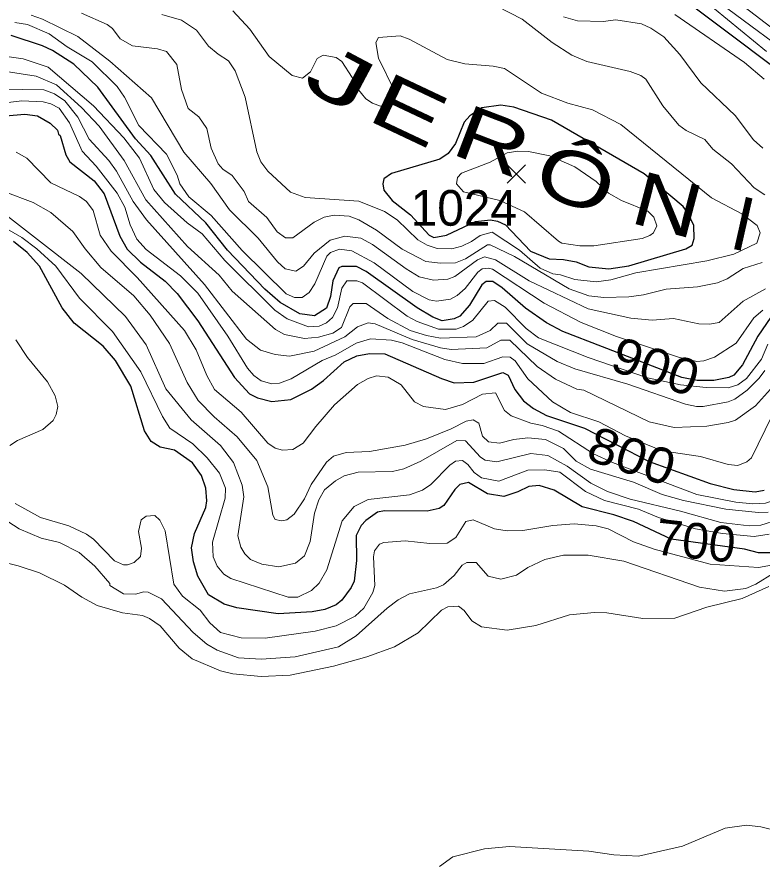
# Model space of a CAD drawing. Extents: x 265 to 291.4, y 7731.5 to 7759.6.
# Drawn here: x 280.28 to 281.951, y 7755.701 to 7757.596 of the extents above; entities that cross this region are included whole.
import ezdxf
from ezdxf.enums import TextEntityAlignment as Align

# ---------------------------------------------------------------- set-up
doc = ezdxf.new("R2010")
doc.units = 0
doc.header["$LTSCALE"] = 0.032
for name, color, linetype, lineweight in [('1', 7, 'Continuous', 25), ('2', 7, 'Continuous', 13), ('21', 7, 'Continuous', 25), ('61', 7, 'Continuous', 13)]:
    doc.layers.add(name, color=color, linetype=linetype, lineweight=lineweight)

msp = doc.modelspace()

# ---------------------------------------------------------------- linework, layer by layer
at = {"layer": '1'}
for points in [[(280.6399, 7758.3559), (280.6709, 7758.3105), (280.69, 7758.297), (280.7163, 7758.2843), (280.8165, 7758.2652), (280.8658, 7758.2413), (280.9358, 7758.1944), (281.0393, 7758.1172), (281.0885, 7758.0679), (281.149, 7758.0265), (281.2429, 7757.9534), (281.3081, 7757.8794), (281.3622, 7757.8332), (281.4099, 7757.8133), (281.5325, 7757.7958), (281.585, 7757.772), (281.6398, 7757.729), (281.7313, 7757.6693), (281.9867, 7757.4761)], [(281.9707, 7756.9224), (281.9413, 7756.8795), (281.9071, 7756.8158), (281.8872, 7756.7927), (281.8761, 7756.7872), (281.8427, 7756.7808), (281.8053, 7756.7808), (281.7712, 7756.7874), (281.5038, 7756.8906), (281.4672, 7756.9097), (281.4203, 7756.9423), (281.3678, 7756.9884), (281.3471, 7757.0027), (281.332, 7757.0027), (281.3224, 7756.9948), (281.2946, 7756.9495), (281.2731, 7756.9248), (281.2604, 7756.9184), (281.2333, 7756.9144), (281.2127, 7756.9224), (281.1776, 7756.9431), (281.0631, 7757.025), (281.0416, 7757.0361), (281.009, 7757.0361), (281.0019, 7757.033), (280.9883, 7757.0036), (280.9835, 7756.9686), (280.974, 7756.9423), (280.9477, 7756.9256), (280.9144, 7756.9303), (280.8706, 7756.955), (280.8364, 7756.9853), (280.7521, 7757.0728), (280.7035, 7757.134), (280.6359, 7757.1984), (280.5802, 7757.2852), (280.546, 7757.3225), (280.4617, 7757.4379), (280.4076, 7757.4896), (280.3599, 7757.5206), (280.3376, 7757.5309), (280.2676, 7757.554)], [(280.2549, 7757.3742), (280.2979, 7757.3774), (280.3265, 7757.3742), (280.3551, 7757.3575), (280.371, 7757.3416), (280.3734, 7757.3329), (280.3774, 7757.3297), (280.3901, 7757.2868), (280.3988, 7757.2708), (280.4538, 7757.2279), (280.476, 7757.1992), (280.511, 7757.1038), (280.5277, 7757.0752), (280.5572, 7757.0457), (280.6129, 7757.0035), (280.6399, 7756.9757), (280.686, 7756.9145), (280.768, 7756.7872), (280.8014, 7756.7506), (280.8197, 7756.7418), (280.8515, 7756.7331), (280.8945, 7756.7378), (280.9406, 7756.7609), (280.9676, 7756.7808), (281.0138, 7756.8222), (281.0424, 7756.8357), (281.0711, 7756.8413), (281.1053, 7756.8405), (281.2318, 7756.7848), (281.2604, 7756.7752), (281.3049, 7756.7768), (281.3693, 7756.7983), (281.3813, 7756.7927), (281.3964, 7756.7601), (281.4163, 7756.7346), (281.4386, 7756.7179), (281.4672, 7756.702), (281.5531, 7756.6734), (281.6977, 7756.5989), (281.8347, 7756.5493), (281.8872, 7756.5358), (281.935, 7756.531), (281.9557, 7756.5342)], [(281.3718, 7756.5207), (281.3352, 7756.5262), (281.293, 7756.5517), (281.2731, 7756.5469), (281.262, 7756.5358), (281.2373, 7756.5), (281.227, 7756.4936), (281.1999, 7756.4873), (281.1045, 7756.4881), (281.0886, 7756.4849), (281.0623, 7756.4666), (281.052, 7756.4554), (281.0408, 7756.4332), (281.0416, 7756.3767), (281.036, 7756.3306), (281.0297, 7756.3163), (281.009, 7756.2876), (280.9963, 7756.2773), (280.9708, 7756.2669), (280.9422, 7756.2614), (280.8658, 7756.2574), (280.7736, 7756.2709), (280.7449, 7756.2789), (280.7099, 7756.2996), (280.686, 7756.3417), (280.6765, 7756.3735), (280.6717, 7756.4054), (280.6781, 7756.4372), (280.7035, 7756.496), (280.7059, 7756.5104), (280.7035, 7756.539), (280.694, 7756.5676), (280.6741, 7756.5955), (280.6335, 7756.6241), (280.6017, 7756.6312), (280.581, 7756.644), (280.5667, 7756.6679), (280.5357, 7756.7681), (280.5015, 7756.8254), (280.4736, 7756.8572), (280.4084, 7756.9089), (280.3814, 7756.9431), (280.3312, 7757.037), (280.3034, 7757.0672), (280.2724, 7757.0918)], [(281.6184, 7756.4793), (281.5476, 7756.4968), (281.4847, 7756.5342), (281.4513, 7756.5453), (281.4282, 7756.543), (281.4036, 7756.531), (281.3718, 7756.5207)], [(281.9859, 7756.3942), (281.9429, 7756.3942), (281.9113, 7756.4021), (281.747, 7756.4247), (281.6629, 7756.4642), (281.6184, 7756.4793)]]:
    msp.add_lwpolyline(points, dxfattribs=at)
msp.add_lwpolyline([(281.2431, 7757.106), (281.3082, 7757.1372), (281.342, 7757.1406), (281.358, 7757.1379), (281.3759, 7757.1293), (281.4318, 7757.0708), (281.4736, 7757.0529), (281.5054, 7757.0521), (281.534, 7757.0465), (281.5627, 7757.0354), (281.6072, 7757.0306), (281.6518, 7757.0377), (281.7798, 7757.0759), (281.7942, 7757.0839), (281.7989, 7757.099), (281.7981, 7757.1277), (281.7846, 7757.1563), (281.7742, 7757.1706), (281.6868, 7757.2438), (281.4791, 7757.3639), (281.394, 7757.3933), (281.3654, 7757.3981), (281.3224, 7757.3917), (281.2954, 7757.3742), (281.2826, 7757.3599), (281.2636, 7757.3122), (281.2468, 7757.2891), (281.2286, 7757.2764), (281.1204, 7757.2446), (281.1029, 7757.2326), (281.1005, 7757.2215), (281.1029, 7757.2072), (281.1219, 7757.1841), (281.1625, 7757.1523), (281.2047, 7757.1061), (281.215, 7757.1014)], close=True, dxfattribs=at)
at = {"layer": '2'}
for points in [[(281.5993, 7757.8173), (281.7902, 7757.6805), (281.8252, 7757.6503), (281.9914, 7757.527)], [(282.0058, 7757.5461), (281.7822, 7757.7179)], [(281.9604, 7757.5182), (281.7568, 7757.6861)], [(281.9509, 7757.0449), (281.9087, 7757.0314), (281.8729, 7757.0083), (281.8506, 7756.9996), (281.8061, 7756.9908), (281.7361, 7756.9853), (281.6852, 7756.9725), (281.6518, 7756.9677), (281.5961, 7756.9669), (281.5627, 7756.9701), (281.5181, 7756.986), (281.3956, 7757.0584), (281.3415, 7757.0847), (281.3352, 7757.0847), (281.2859, 7757.0529), (281.2636, 7757.0441), (281.2302, 7757.0433), (281.1968, 7757.0473), (281.1443, 7757.0751), (281.0862, 7757.1173), (281.0472, 7757.1404), (281.0249, 7757.1491), (280.9915, 7757.1515), (280.9693, 7757.1467), (280.947, 7757.1356), (280.8992, 7757.1006), (280.8825, 7757.1006), (280.8634, 7757.1141), (280.8404, 7757.1459), (280.7998, 7757.1817), (280.7895, 7757.204), (280.7632, 7757.2398), (280.7417, 7757.2541), (280.7314, 7757.2661), (280.7155, 7757.3011), (280.7059, 7757.3456), (280.6884, 7757.3719), (280.6646, 7757.3902), (280.6494, 7757.4331), (280.6391, 7757.4888), (280.6153, 7757.5182), (280.5954, 7757.5238), (280.5397, 7757.531), (280.5118, 7757.5468), (280.4943, 7757.5699), (280.4824, 7757.5787), (280.4251, 7757.6041)], [(280.6049, 7757.601), (280.6495, 7757.5882), (280.6829, 7757.5659), (280.7099, 7757.5302), (280.7314, 7757.5119), (280.7545, 7757.4975), (280.7696, 7757.4745), (280.7918, 7757.4156), (280.8181, 7757.2931), (280.8268, 7757.2708), (280.8428, 7757.2502), (280.8936, 7757.2024), (280.9263, 7757.1905), (281.0472, 7757.1825), (281.1045, 7757.1595), (281.1331, 7757.1404), (281.1792, 7757.0958), (281.1999, 7757.0839), (281.2222, 7757.0767), (281.2556, 7757.0759), (281.2779, 7757.0815), (281.2994, 7757.0918), (281.3185, 7757.1054), (281.3455, 7757.1133), (281.4068, 7757.0727), (281.453, 7757.0322), (281.4815, 7757.0196), (281.499, 7757.0171), (281.5309, 7757.0067), (281.5786, 7757.002), (281.612, 7757.0059), (281.6677, 7757.0218), (281.8268, 7757.0489), (281.8872, 7757.064), (281.9389, 7757.0887), (281.9469, 7757.1117), (281.9397, 7757.1277), (281.9055, 7757.1539), (281.8371, 7757.1897), (281.6343, 7757.3544), (281.5706, 7757.387), (281.515, 7757.4021), (281.4561, 7757.4251), (281.3734, 7757.48), (281.3479, 7757.4856), (281.2843, 7757.4904), (281.2445, 7757.4999), (281.1594, 7757.5461), (281.1395, 7757.5532), (281.091, 7757.5493), (281.0846, 7757.5381), (281.0909, 7757.5031), (281.1275, 7757.4283), (281.1259, 7757.4116), (281.1164, 7757.4005), (281.0957, 7757.3957), (281.0774, 7757.4021), (281.0623, 7757.4124), (281.0432, 7757.4363), (281.0321, 7757.4602), (281.009, 7757.496), (280.9963, 7757.5047), (280.9669, 7757.5103), (280.9533, 7757.5023), (280.9382, 7757.4729), (280.9207, 7757.4586), (280.8977, 7757.4641), (280.8459, 7757.5071), (280.8022, 7757.5684), (280.764, 7757.6097)], [(281.3574, 7757.6192), (281.4131, 7757.5906), (281.48, 7757.5381), (281.5245, 7757.5103), (281.5579, 7757.496), (281.655, 7757.4737), (281.6788, 7757.4641), (281.69, 7757.4562), (281.7281, 7757.3965), (281.7639, 7757.3528), (281.7806, 7757.3408), (281.8228, 7757.3209), (281.8403, 7757.2995), (281.8825, 7757.2661), (281.9334, 7757.2128), (281.9572, 7757.1968)], [(280.3122, 7757.5994), (280.3376, 7757.5906), (280.4172, 7757.5516), (280.4888, 7757.4967), (280.5818, 7757.414), (280.6542, 7757.2923), (280.7147, 7757.2223), (280.7568, 7757.1634), (280.8213, 7757.0998), (280.8642, 7757.0465), (280.8817, 7757.0306), (280.9056, 7757.0258), (280.9231, 7757.037), (280.947, 7757.0656)], [(281.9525, 7757.3011), (281.9318, 7757.3202), (281.8904, 7757.3743), (281.8132, 7757.4482), (281.7663, 7757.5111), (281.7305, 7757.5508), (281.7011, 7757.5707), (281.6804, 7757.5803), (281.6231, 7757.589), (281.5945, 7757.5858), (281.5372, 7757.5866), (281.5054, 7757.5962)], [(281.7552, 7757.601), (281.9111, 7757.4936), (281.9556, 7757.4562)], [(280.9485, 7756.9972), (280.9358, 7756.9781), (280.9199, 7756.9669), (280.9024, 7756.9669), (280.8841, 7756.9749), (280.7855, 7757.072), (280.7155, 7757.1507), (280.6654, 7757.1921), (280.6455, 7757.2215), (280.6399, 7757.2406), (280.616, 7757.2883), (280.554, 7757.352), (280.5214, 7757.4156), (280.5047, 7757.4395), (280.449, 7757.4952), (280.3933, 7757.5286), (280.3527, 7757.558), (280.3042, 7757.5787), (280.2756, 7757.5835)], [(280.2629, 7757.5063), (280.2947, 7757.5015), (280.3504, 7757.4832), (280.4522, 7757.3965), (280.5198, 7757.3249), (280.5548, 7757.2788), (280.5874, 7757.2088), (280.6113, 7757.1793), (280.6622, 7757.134), (280.6956, 7757.1093)], [(281.9572, 7756.8031), (281.9445, 7756.7856), (281.9175, 7756.7585), (281.8896, 7756.7386), (281.8745, 7756.7323), (281.8188, 7756.7219), (281.8037, 7756.7219), (281.7791, 7756.7275), (281.6502, 7756.7721), (281.5309, 7756.8063), (281.4911, 7756.823), (281.4243, 7756.8627), (281.3781, 7756.9089), (281.3582, 7756.9089), (281.3415, 7756.8922), (281.3097, 7756.8787), (281.2302, 7756.8755), (281.1983, 7756.881), (281.1618, 7756.8922), (281.1116, 7756.9192), (281.0631, 7756.9534), (281.0345, 7756.9534), (281.0265, 7756.9455), (281.0082, 7756.8993), (280.9883, 7756.8866), (280.9565, 7756.8779), (280.9247, 7756.8747), (280.8802, 7756.8834), (280.8603, 7756.8946), (280.7632, 7756.9805), (280.7338, 7757.0163), (280.663, 7757.0807), (280.5691, 7757.1857), (280.5206, 7757.274), (280.4649, 7757.3504), (280.4251, 7757.3925), (280.3687, 7757.4434), (280.3233, 7757.4625), (280.2565, 7757.4737)], [(280.2438, 7757.4339), (280.3408, 7757.4323), (280.3647, 7757.4236), (280.3877, 7757.4076), (280.4172, 7757.3711), (280.4426, 7757.3218), (280.4864, 7757.274), (280.5039, 7757.2502), (280.5413, 7757.1817), (280.5707, 7757.1404), (280.7011, 7756.9956), (280.795, 7756.8731), (280.8261, 7756.8484), (280.8595, 7756.8389), (280.8913, 7756.8349), (280.947, 7756.846), (281.0154, 7756.8786)], [(282.0034, 7756.7633), (281.927, 7756.6074), (281.9167, 7756.5979), (281.8968, 7756.5899), (281.8745, 7756.5923), (281.8125, 7756.6098), (281.7269, 7756.623), (281.6445, 7756.6562), (281.585, 7756.6877), (281.5213, 7756.7084), (281.4807, 7756.7323), (281.4258, 7756.784), (281.3972, 7756.8246), (281.3861, 7756.8325), (281.3694, 7756.8333), (281.3272, 7756.8182), (281.2795, 7756.8182), (281.2397, 7756.8277), (281.1443, 7756.8651), (281.1204, 7756.8707), (281.0727, 7756.8739), (281.0408, 7756.8643), (280.9955, 7756.8381), (280.9645, 7756.8254), (280.8953, 7756.784), (280.869, 7756.7744), (280.8515, 7756.7729), (280.8277, 7756.78), (280.8117, 7756.792), (280.7974, 7756.8079), (280.7529, 7756.8795), (280.686, 7756.9765), (280.6471, 7757.0155), (280.5699, 7757.0743), (280.5492, 7757.0974), (280.5341, 7757.1292), (280.5222, 7757.169), (280.5047, 7757.2008), (280.4577, 7757.2613), (280.4267, 7757.2947), (280.3981, 7757.3583), (280.375, 7757.391), (280.3567, 7757.4005), (280.3392, 7757.4053), (280.2915, 7757.4076), (280.204, 7757.3973)], [(280.2788, 7757.2923), (280.3026, 7757.2788), (280.3567, 7757.2239), (280.4204, 7757.1929), (280.4363, 7757.1817), (280.4514, 7757.1619), (280.4673, 7757.1062), (280.4919, 7757.0704), (280.55, 7757.0115), (280.6558, 7756.8922), (280.6821, 7756.8492), (280.7059, 7756.792), (280.7234, 7756.7601), (280.7831, 7756.7092), (280.8428, 7756.64), (280.8595, 7756.6289), (280.8754, 7756.6241), (280.8992, 7756.6257), (280.9223, 7756.64), (280.9501, 7756.6774), (280.9923, 7756.7259), (281.044, 7756.7713), (281.0676, 7756.7846), (281.0862, 7756.7906), (281.1124, 7756.788), (281.1419, 7756.7705), (281.1713, 7756.7323), (281.192, 7756.7219), (281.2413, 7756.7156), (281.2795, 7756.7267), (281.324, 7756.7498), (281.3535, 7756.753), (281.3733, 7756.7132), (281.3884, 7756.7012), (281.4322, 7756.6846), (281.4577, 7756.6798), (281.4943, 7756.6671), (281.5728, 7756.6162), (281.6153, 7756.5969), (281.8045, 7756.5247), (281.892, 7756.508), (281.9302, 7756.504)], [(281.9859, 7756.4682), (281.9477, 7756.4562), (281.9222, 7756.4546), (281.8586, 7756.4618), (281.7679, 7756.4873), (281.655, 7756.5143), (281.604, 7756.5318), (281.5667, 7756.5501), (281.5141, 7756.5883), (281.4704, 7756.6122), (281.4322, 7756.6169), (281.3559, 7756.5978), (281.3304, 7756.6018), (281.3193, 7756.6082), (281.2859, 7756.6448), (281.2667, 7756.6456), (281.1856, 7756.5994), (281.1474, 7756.5827), (281.122, 7756.5764), (281.0456, 7756.5748), (281.0138, 7756.5668), (280.9947, 7756.5557), (280.97, 7756.535), (280.9573, 7756.5127), (280.9478, 7756.4833), (280.9374, 7756.4197), (280.9247, 7756.387), (280.9048, 7756.3711), (280.8674, 7756.3624), (280.8292, 7756.3687), (280.8038, 7756.3791), (280.7911, 7756.3918), (280.7823, 7756.4069), (280.7759, 7756.4324), (280.7887, 7756.5199), (280.7855, 7756.5454), (280.7656, 7756.5963), (280.737, 7756.6345), (280.6709, 7756.6925), (280.6144, 7756.7617), (280.5699, 7756.8604), (280.5238, 7756.924), (280.4243, 7757.0203), (280.208, 7757.1889)], [(280.2533, 7757.2032), (280.317, 7757.1793), (280.3567, 7757.1571), (280.406, 7757.1149), (280.4331, 7757.0759), (280.4681, 7757.0338), (280.5421, 7756.9701), (280.5787, 7756.9272), (280.6224, 7756.8636), (280.6622, 7756.7761), (280.6868, 7756.7355), (280.7226, 7756.6989), (280.7744, 7756.6543), (280.8181, 7756.601), (280.8428, 7756.5422), (280.8539, 7756.4785), (280.8595, 7756.469), (280.8738, 7756.4658), (280.8857, 7756.4682), (280.9016, 7756.4809), (280.9247, 7756.5151), (280.9398, 7756.547), (280.974, 7756.5971), (280.9899, 7756.6106), (281.0186, 7756.6193), (281.0711, 7756.6209), (281.1506, 7756.6352), (281.1983, 7756.6496), (281.254, 7756.6718), (281.2874, 7756.6893), (281.3033, 7756.6925), (281.3161, 7756.6846), (281.324, 7756.6559), (281.3376, 7756.6432), (281.3622, 7756.64)], [(280.227, 7757.138), (280.2915, 7757.1014), (280.3249, 7757.0759), (280.3679, 7757.037), (280.4203, 7756.9654), (280.4943, 7756.8906), (280.558, 7756.7999), (280.6065, 7756.6997), (280.6232, 7756.6734), (280.6749, 7756.6384), (280.7067, 7756.6074), (280.7346, 7756.5724), (280.7481, 7756.539), (280.7473, 7756.5167), (280.7187, 7756.4181), (280.7203, 7756.3847), (280.729, 7756.364), (280.7441, 7756.3465), (280.76, 7756.3361), (280.8881, 7756.2948), (280.9104, 7756.2948), (280.9406, 7756.3099), (280.9581, 7756.3258), (280.9748, 7756.356)], [(280.6956, 7757.1093), (280.7465, 7757.0497), (280.8587, 7756.9383), (280.8865, 7756.9184), (280.9342, 7756.9009), (280.9581, 7756.9025), (280.974, 7756.9097)], [(280.947, 7757.0656), (280.9828, 7757.095), (281.0154, 7757.1038), (281.0512, 7757.0998), (281.0774, 7757.0855), (281.153, 7757.0306), (281.1824, 7757.0131)], [(281.1681, 7756.9797), (281.0814, 7757.0441), (281.0313, 7757.0712), (281.0034, 7757.0751), (280.9836, 7757.0672), (280.9748, 7757.0592), (280.9485, 7756.9972)], [(281.1824, 7757.0131), (281.2143, 7757.0051), (281.2461, 7757.0075), (281.262, 7757.0139), (281.3129, 7757.0513), (281.3288, 7757.0576), (281.3535, 7757.0513), (281.429, 7757.0043), (281.5611, 7756.9415), (281.6565, 7756.92), (281.7043, 7756.916), (281.752, 7756.9192), (281.8093, 7756.9073), (281.8331, 7756.9065), (281.8546, 7756.9105), (281.9087, 7756.9582), (281.9588, 7756.986)], [(281.9525, 7756.9383), (281.9326, 7756.9208), (281.8928, 7756.8643), (281.8443, 7756.8325), (281.8204, 7756.8246), (281.8045, 7756.823), (281.7635, 7756.8326), (281.6247, 7756.8794), (281.5452, 7756.9105), (281.4625, 7756.9542), (281.3463, 7757.0298), (281.3368, 7757.0322), (281.3232, 7757.0306), (281.3137, 7757.0234), (281.285, 7756.9869), (281.2676, 7756.9709), (281.2524, 7756.963), (281.2206, 7756.9582), (281.2047, 7756.9614), (281.1681, 7756.9797)], [(280.974, 7756.9097), (280.9875, 7756.9216), (280.9987, 7756.9431), (281.009, 7756.9877), (281.0202, 7757.0036), (281.0424, 7757.0043), (281.0552, 7756.9996), (281.1554, 7756.9248), (281.1777, 7756.9129), (281.2254, 7756.8954), (281.2652, 7756.8954), (281.2811, 7756.9017), (281.3026, 7756.916), (281.3368, 7756.9582), (281.3511, 7756.9598), (281.3749, 7756.9447), (281.4219, 7756.897), (281.4497, 7756.8763), (281.5611, 7756.8317), (281.6942, 7756.7863), (281.7679, 7756.7704), (281.8256, 7756.7644), (281.8745, 7756.7641), (281.8968, 7756.7705), (281.9159, 7756.7848), (281.9493, 7756.8286), (281.9636, 7756.862)], [(281.0154, 7756.8786), (281.044, 7756.9009), (281.0679, 7756.9097), (281.0838, 7756.9073), (281.1665, 7756.8723), (281.2302, 7756.854), (281.254, 7756.85)], [(280.278, 7756.8715), (280.3042, 7756.8317), (280.3488, 7756.7776), (280.3663, 7756.7458), (280.3718, 7756.722), (280.3686, 7756.7045), (280.3615, 7756.6909), (280.3384, 7756.6702), (280.282, 7756.6456), (280.2645, 7756.6344)], [(281.254, 7756.85), (281.3336, 7756.854), (281.3654, 7756.8707), (281.3853, 7756.8707), (281.4465, 7756.8118), (281.4879, 7756.7832), (281.5356, 7756.7609), (281.5515, 7756.7585), (281.6979, 7756.6877), (281.7536, 7756.675), (281.8268, 7756.6782), (281.8745, 7756.6861), (281.8912, 7756.6917), (281.9358, 7756.7235), (281.97, 7756.7609)], [(281.3622, 7756.64), (281.394, 7756.648), (281.4259, 7756.6519), (281.4656, 7756.648), (281.5054, 7756.6281), (281.534, 7756.5994), (281.5659, 7756.5819)], [(281.2079, 7756.5469), (281.2508, 7756.5907), (281.2636, 7756.5994), (281.2795, 7756.601), (281.2914, 7756.5923), (281.3057, 7756.574), (281.3216, 7756.5621), (281.3606, 7756.5549), (281.4259, 7756.5796), (281.464, 7756.5803), (281.4975, 7756.5748), (281.5547, 7756.5318), (281.5977, 7756.5111), (281.674, 7756.492), (281.7186, 7756.473), (281.8013, 7756.4476), (281.8624, 7756.4376), (281.9334, 7756.4308), (281.9668, 7756.4356)], [(281.9302, 7756.504), (281.9588, 7756.5056), (281.9819, 7756.5127), (282.005, 7756.5326), (282.024, 7756.5578), (282.0319, 7756.5791), (282.0379, 7756.6103)], [(281.5659, 7756.5819), (281.6629, 7756.5525), (281.7266, 7756.5247), (281.7743, 7756.5111), (281.8697, 7756.492), (281.9429, 7756.4841), (281.9644, 7756.4849)], [(280.9748, 7756.356), (281.0098, 7756.4658), (281.0361, 7756.4976), (281.0679, 7756.5135), (281.1602, 7756.5239), (281.1896, 7756.5342), (281.2079, 7756.5469)], [(280.2764, 7756.5048), (280.3329, 7756.473), (280.3965, 7756.4547), (280.4363, 7756.4356), (280.4522, 7756.4244), (280.4991, 7756.3759), (280.519, 7756.3672), (280.5286, 7756.3672), (280.5429, 7756.3727), (280.5572, 7756.3855), (280.5596, 7756.4046), (280.5532, 7756.4419), (280.5588, 7756.4682), (280.5699, 7756.4761), (280.5898, 7756.4777)], [(281.6406, 7756.3751), (281.5611, 7756.3886), (281.5054, 7756.3886), (281.464, 7756.3791), (281.4259, 7756.3608), (281.4004, 7756.3441), (281.3654, 7756.3353), (281.3368, 7756.3417), (281.3097, 7756.3727), (281.289, 7756.3727), (281.2787, 7756.3664), (281.2604, 7756.3433), (281.2365, 7756.3226), (281.2206, 7756.3155), (281.1602, 7756.3019), (281.1347, 7756.2884), (281.11, 7756.2701), (281.0408, 7756.2081), (281.0011, 7756.1834), (280.904, 7756.1611), (280.8277, 7756.1556), (280.7767, 7756.1587), (280.729, 7756.1754), (280.7059, 7756.189), (280.6757, 7756.2152), (280.6041, 7756.2908), (280.5747, 7756.3059), (280.5651, 7756.3067), (280.5461, 7756.3011), (280.519, 7756.3019), (280.4888, 7756.321), (280.4888, 7756.325), (280.4553, 7756.364), (280.4196, 7756.395), (280.3758, 7756.4173), (280.3345, 7756.4268), (280.2851, 7756.4475), (280.2469, 7756.4722)], [(280.5898, 7756.4777), (280.6009, 7756.4674), (280.6129, 7756.4435), (280.6319, 7756.3234), (280.6518, 7756.2972), (280.6908, 7756.2653), (280.7131, 7756.2367)], [(280.7131, 7756.2367), (280.737, 7756.2152), (280.7831, 7756.2033), (280.8372, 7756.2025), (280.9486, 7756.2184), (280.9963, 7756.2303), (281.0385, 7756.2518), (281.0583, 7756.2701), (281.0782, 7756.3051), (281.083, 7756.321), (281.0798, 7756.3847), (281.0822, 7756.3982), (281.0933, 7756.4133), (281.1029, 7756.4173), (281.1506, 7756.4212), (281.2063, 7756.4149), (281.2445, 7756.4157), (281.2644, 7756.4284), (281.2866, 7756.4642), (281.3034, 7756.4682), (281.3511, 7756.4475), (281.3797, 7756.4435), (281.4147, 7756.4443), (281.4815, 7756.4555), (281.5293, 7756.4594), (281.5786, 7756.4547), (281.6056, 7756.4475), (281.6629, 7756.4189), (281.7091, 7756.4022), (281.8348, 7756.3686), (281.9429, 7756.3608), (281.9843, 7756.3687)], [(280.2318, 7756.3775), (280.2835, 7756.3648), (280.3313, 7756.3489), (280.387, 7756.3218), (280.4259, 7756.2948), (280.4601, 7756.2757), (280.5174, 7756.2598), (280.562, 7756.2534), (280.5779, 7756.247), (280.6017, 7756.2303), (280.6439, 7756.1802), (280.6733, 7756.1564), (280.737, 7756.1293), (280.764, 7756.1229), (280.8277, 7756.1166), (280.8929, 7756.1198), (280.9899, 7756.1397), (281.0647, 7756.1611), (281.1267, 7756.1834), (281.18, 7756.2144), (281.2325, 7756.2653), (281.2461, 7756.2733), (281.2699, 7756.2741), (281.2827, 7756.2645), (281.3002, 7756.2415), (281.3216, 7756.2279), (281.3797, 7756.2208), (281.4434, 7756.2311), (281.5189, 7756.255), (281.5754, 7756.2606), (281.6025, 7756.2598), (281.6836, 7756.247), (281.7552, 7756.2478), (281.8268, 7756.2725), (281.9063, 7756.2916), (281.966, 7756.3186)], [(282.0336, 7756.3703), (281.9779, 7756.3489), (281.9366, 7756.3234), (281.9143, 7756.3139), (281.8666, 7756.3083), (281.8109, 7756.317), (281.6406, 7756.3751)], [(282.0097, 7755.7642), (281.9477, 7755.7793), (281.9159, 7755.7833), (281.8681, 7755.7769), (281.7727, 7755.7363), (281.674, 7755.7141), (281.6184, 7755.7172), (281.5627, 7755.7252), (281.3845, 7755.7355), (281.3288, 7755.73), (281.2572, 7755.7125), (281.2278, 7755.691)]]:
    msp.add_lwpolyline(points, dxfattribs=at)
msp.add_lwpolyline([(281.4179, 7757.1586), (281.3629, 7757.1838), (281.2818, 7757.2033), (281.266, 7757.2215), (281.2683, 7757.2358), (281.2771, 7757.2454), (281.3415, 7757.27), (281.3797, 7757.2907), (281.4036, 7757.2947), (281.4274, 7757.2939), (281.4752, 7757.2844), (281.5309, 7757.2597), (281.5786, 7757.2263), (281.6064, 7757.2008), (281.6359, 7757.1841), (281.6947, 7757.1603), (281.7083, 7757.1467), (281.7146, 7757.1269), (281.7074, 7757.1117), (281.6995, 7757.1054), (281.682, 7757.099), (281.5738, 7757.0823), (281.542, 7757.0823), (281.5022, 7757.0887), (281.4943, 7757.0926)], close=True, dxfattribs=at)
at = {"layer": '21'}
for p, q in [((281.379, 7757.264), (281.4202, 7757.2228)), ((281.4202, 7757.264), (281.379, 7757.2228))]:
    msp.add_line(p, q, dxfattribs=at)

# ---------------------------------------------------------------- texts
at = {"layer": '61'}
for s, height, rotation, width, p in [('J', 0.12, 332.053, 1.75, (280.9779, 7757.4057)), ('E', 0.12, 334.712, 1.5, (281.1339, 7757.3324)), ('R', 0.12, 339.049, 1.4, (281.3252, 7757.2613)), ('Ô', 0.12, 340.425, 1.4, (281.5133, 7757.1758)), ('N', 0.12, 345.332, 1.3, (281.7237, 7757.1163)), ('900', 0.08, 341.766, 1.1, (281.6994, 7756.7739)), ('800', 0.08, 341.843, 1.1, (281.6462, 7756.5731))]:
    msp.add_text(s, height=height, rotation=rotation, dxfattribs=dict(at, width=width)).set_placement(p, align=Align.CENTER)
msp.add_text('1024', height=0.08, dxfattribs=at).set_placement((281.2822, 7757.1275), align=Align.CENTER)
for s, height, rotation, p in [('I', 0.12, 347.302, (281.8955, 7757.0733)), ('700', 0.08, 353.77, (281.7977, 7756.3813))]:
    msp.add_text(s, height=height, rotation=rotation, dxfattribs=at).set_placement(p, align=Align.CENTER)

doc.saveas('drawing.dxf')
